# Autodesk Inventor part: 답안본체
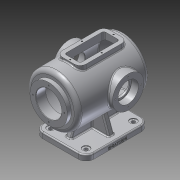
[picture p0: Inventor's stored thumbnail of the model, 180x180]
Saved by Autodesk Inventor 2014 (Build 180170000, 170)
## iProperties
Created: 2021-11
Part Number: 답안본체
Material: 알루미늄 6061
Document SubType Name: Modeling
Designer: kb
Density: 2.71 g/cm^3
Appearance: 알루미늄 - 평지
Mass: 3553.3 g
Surface Area: 2413.01 cm^2
Volume: 1311.18 cm^3
Author: kb
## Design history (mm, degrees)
sketch "스케치1"
  geometry: L1 (0, 0)-(220, 0); L2 (185.993, 65)-(10, 65); L3 (10, 65)-(10, 47.5); L4 (10, 47.5)-(0, 47.5); L5 (0, 47.5)-(0, 32.5); L6 (0, 32.5)-(25, 32.5); L7 (25, 32.5)-(25, 52); L8 (28, 55)-(179.75, 55); A1 r 100 centre (110, 0) between (210, 0) and (185.993, 65); A2 r 90 centre (110, 0) between (200, 0) and (182.155, 53.793); A3 r 3 centre (28, 52) between (28, 55) and (25, 52); A4 r 3 centre (179.75, 52) between (182.155, 53.793) and (179.75, 55); 2 further points
  constraints: 16 end point, 9 point on circle, 5 point on line, 4 centre point, 4 perpendicular, 4 tangent, 2 parallel, 1 coincident, 1 horizontal, 1 midpoint, 1 vertical alignment
  dimensions: "d0" = 130 diameter of L2 L1; "d2" = 95 diameter of L4 L1; "d3" = 110 diameter of L8 L1; "d4" = 65 diameter of L6 L1; "d6" = 10 distance of L3.end L4.end; "d9" = 25 distance between parallel lines of L7 L5; "d13" = 100 radius of A1; "d14" = 10 radial gap between concentric circles of A1 A2; "d15" = 210 distance from line of A1.start L5; "d17" = 3 radius of A3; "d18" = 3 radius of A4
revolve "회전1" sketch "스케치1" stored, may be unused: angle "d10" = 90 deg
fillet "모깎기1" dims "d16" = 10
node "작업 평면1"
sketch "스케치2"
  geometry: L1 (47.5, 0)-(-47.5, 0) reference; L2 (-45, 190)-(45, 190); L3 (65, 170)-(65, 50); L4 (45, 30)-(-45, 30); L5 (-65, 50)-(-65, 170); A1 r 100 centre (0, 110) between (61.111, 189.154) and (-61.111, 189.154) reference; A2 r 20 centre (-45, 170) between (-45, 190) and (-65, 170); A3 r 20 centre (-45, 50) between (-65, 50) and (-45, 30); A4 r 20 centre (45, 50) between (45, 30) and (65, 50); A5 r 20 centre (45, 170) between (65, 170) and (45, 190); 9 further points
  constraints: 8 end point, 8 point on circle, 8 tangent, 6 point on line, 4 centre point, 4 coincident, 3 equal radius, 2 parallel, 1 horizontal, 1 midpoint, 1 perpendicular, 1 vertical alignment
  dimensions: "d20" = 130 distance of point (-65, 190) point (65, 190); "d21" = 160 distance of point (65, 190) point (65, 30); "d22" = 30 distance between parallel lines of L4 L1; "d23" = 20 radius of A2
extrude "돌출1" join sketch "스케치2" distance "d24" = 14; taper "d25" = 0 deg
sketch "스케치3"
  geometry: A1 r 20 centre (-45, 50) between (-65, 50) and (-45, 30) reference; A2 r 20 centre (45, 50) between (45, 30) and (65, 50) reference; A3 r 20 centre (45, 170) between (65, 170) and (45, 190) reference; A4 r 20 centre (-45, 170) between (-45, 190) and (-65, 170) reference; 5 further points
  constraints: 4 coincident
hole "구멍1" sketch "스케치3" at (-45, 50), (45, 170), (45, 50), (-45, 170) diameter "d26" = 9; stored, may be unused: countersink angle "d30" = 90 deg, drill point angle "d32" = 118 deg; dims "d27" = 6, "d28" = 18, "d29" = 2, "d31" = 12
node "작업 평면2"
sketch "스케치4"
  geometry: L1 (45, 114)-(45, -1.6); L2 (90, 14)-(0, 14) reference; L3 (11.261, 58.442)-(-5, 13.765); L4 (78.739, 58.442)-(95, 13.765); L5 (110, 14)-(90, 14) reference; L6 (-9, 14)-(9, 14) reference; L7 (-5, 13.765)-(95, 13.765); L8 (94.5, 12)-(85.5, 12) reference; A1 r 65 centre (45, 114) between (11.261, 58.442) and (11.261, 58.442) reference; A2 r 65 centre (45, 114) between (11.261, 58.442) and (78.739, 58.442); 2 further points
  constraints: 8 end point, 4 point on circle, 2 symmetric about line, 1 centre point, 1 concentric, 1 midpoint, 1 parallel, 1 perpendicular, 1 vertical alignment, 1 other
  dimensions: "d40" = 100 distance of L4.end L3.end; "d41" = 110 deg angle of L5 L4; "d42" = 110 deg angle of L6 L3 (derived); "d43" = 14.17568 distance from line of L5.start L4; "d44" = 15.60038 distance from line of L1.end L2
sketch "스케치5"
  geometry: 1 further point
extrude "돌출3" join sketch "스케치4" stored distance "d45" = 14; taper "d46" = 0 deg
sketch "스케치6"
  geometry: L1 (20, -65)-(181.239, -65) reference; L2 (170, -100)-(50, -100) reference; L3 (62.739, -65)-(50, -100); L4 (41, -100)-(59, -100) reference; L5 (190, -100)-(170, -100) reference; L6 (157.261, -65)-(170, -100); L7 (103, -100)-(117, -100) reference; L8 (103, -55.558)-(103, -100) reference; L9 (117, -55.558)-(103, -55.558) reference; L10 (117, -100)-(117, -55.558) reference; L11 (117, -100)-(117, -55.558) reference; L12 (110, -55.558)-(110, -100); 1 further point
  constraints: 6 end point, 3 midpoint, 2 point on line, 1 other
  dimensions: "d117" = 120 distance of L2.start L2.end (derived); "d118" = 110 deg angle of L5 L6
  node "투영된 루프1"
feature "리브1" dims "d50" = 1, "d51" = 14, "d52" = 0, "d53" = 0, "d54" = 1, "d55" = 1
feature "리브2" dims "d56" = 1, "d57" = 14, "d58" = 0, "d59" = 0, "d60" = 1, "d61" = 1
node "작업 평면3"
sketch "스케치7"
  geometry: L1 (0, -47.5)-(0, 47.5) reference; C1 r 40 at (127, 0); 2 further points
  constraints: 1 centre point, 1 horizontal alignment, 1 midpoint
  dimensions: "d63" = 127 distance from line of C1.centre L1; "d64" = 80 diameter of C1
extrude "돌출4" join sketch "스케치7" stored distance "d65" = 14; taper "d66" = 0 deg
hole "구멍2" diameter "d69" = 42; stored, may be unused: countersink angle "d73" = 90 deg, drill point angle "d75" = 118 deg; dims "d67" = 10, "d68" = 10, "d70" = 6, "d71" = 52, "d72" = 18, "d74" = 12
fillet "모깎기2" dims "d76" = 0.3
node "작업 평면4"
sketch "스케치8"
  geometry: L1 (-15, 170)-(15, 170); L2 (30, 155)-(30, 65); L3 (15, 50)-(-15, 50); L4 (-30, 65)-(-30, 155); L5 (47.5, 0)-(-47.5, 0) reference; A1 r 15 centre (-15, 155) between (-15, 170) and (-30, 155); A2 r 15 centre (-15, 65) between (-30, 65) and (-15, 50); A3 r 15 centre (15, 65) between (15, 50) and (30, 65); A4 r 15 centre (15, 155) between (30, 155) and (15, 170); 5 further points
  constraints: 8 end point, 8 point on circle, 8 tangent, 6 point on line, 4 centre point, 3 equal radius, 2 parallel, 1 horizontal, 1 midpoint, 1 perpendicular, 1 vertical alignment
  dimensions: "d78" = 120 distance of point (30, 170) point (30, 50); "d79" = 60 distance of point (-30, 170) point (30, 170); "d80" = 50 distance between parallel lines of L3 L5; "d81" = 15 radius of A1
extrude "돌출5" join sketch "스케치8" stored distance "d82" = 14; taper "d83" = 0 deg
sketch "스케치9"
  geometry: L1 (-30, 155)-(-30, 65) reference; L2 (-15, 50)-(15, 50) reference; L3 (30, 65)-(30, 155) reference; L4 (15, 170)-(-15, 170) reference; L5 (20, 155)-(20, 65); L6 (15, 60)-(-15, 60); L7 (-20, 65)-(-20, 155); L8 (-15, 160)-(15, 160); A1 r 15 centre (-15, 65) between (-30, 65) and (-15, 50) reference; A2 r 15 centre (15, 65) between (15, 50) and (30, 65) reference; A3 r 15 centre (15, 155) between (30, 155) and (15, 170) reference; A4 r 15 centre (-15, 155) between (-15, 170) and (-30, 155) reference; A5 r 5 centre (15, 155) between (20, 155) and (15, 160); A6 r 5 centre (15, 65) between (15, 60) and (20, 65); A7 r 5 centre (-15, 65) between (-20, 65) and (-15, 60); A8 r 5 centre (-15, 155) between (-15, 160) and (-20, 155); 1 further point
  constraints: 8 end point, 8 point on circle, 4 centre point, 7 other
  dimensions: "d84" = 10 distance between parallel lines of L3 L5
extrude "돌출6" cut sketch "스케치9" stored distance "d85" = 14; taper "d86" = 0 deg
sketch "스케치10"
  geometry: L1 (-30, 155)-(-30, 65) reference; L2 (-15, 50)-(15, 50) reference; L3 (30, 65)-(30, 155) reference; L4 (15, 170)-(-15, 170) reference; L5 (25, 155)-(25, 65); L6 (15, 55)-(-15, 55); L7 (-25, 65)-(-25, 155); L8 (-15, 165)-(15, 165); L9 (-25, 110)-(25, 110); L10 (0, 165)-(0, 55); A1 r 15 centre (-15, 65) between (-30, 65) and (-15, 50) reference; A2 r 15 centre (15, 65) between (15, 50) and (30, 65) reference; A3 r 15 centre (15, 155) between (30, 155) and (15, 170) reference; A4 r 15 centre (-15, 155) between (-15, 170) and (-30, 155) reference; A5 r 10 centre (15, 65) between (15, 55) and (25, 65); A6 r 10 centre (-15, 65) between (-25, 65) and (-15, 55); A7 r 10 centre (-15, 155) between (-15, 165) and (-25, 155); A8 r 10 centre (15, 155) between (25, 155) and (15, 165); 9 further points; 1 other entity
  constraints: 12 end point, 8 point on circle, 5 coincident, 4 centre point, 4 midpoint, 8 other
  dimensions: "d87" = 5 distance between parallel lines of L3 L5
hole "구멍3" sketch "스케치10" at (-25, 110), (0, 55), (25, 110), (0, 165) diameter "d88" = 3.242; stored, may be unused: countersink angle "d92" = 90 deg, drill point angle "d94" = 118 deg; dims "d89" = 9, "d90" = 52, "d91" = 18, "d93" = 11
sketch "스케치11"
  geometry: C1 r 26 at (0, 0) reference; C2 r 40 at (0, 0) reference; A1 r 32.5 centre (0, 0) between (0, 32.5) and (-32.5, 0); 3 further points
  constraints: 4 point on circle, 2 horizontal alignment, 2 vertical alignment, 1 centre point, 1 coincident
  dimensions: "d95" = 65 diameter of A1
hole "구멍4" sketch "스케치11" at (-32.5, 0), (0, -32.5), (32.5, 0), (0, 32.5) diameter "d96" = 3.242; stored, may be unused: countersink angle "d100" = 90 deg, drill point angle "d102" = 118 deg; dims "d97" = 11, "d98" = 52, "d99" = 18, "d101" = 13
sketch "스케치12"
  geometry: C1 r 32.5 at (0, 0) reference; C2 r 47.5 at (0, 0) reference; A1 r 40 centre (0, 0) between (0, 40) and (0, -40); 2 further points
  constraints: 4 point on circle, 2 horizontal alignment, 2 vertical alignment, 1 centre point, 1 coincident
  dimensions: "d103" = 80 diameter of A1
hole "구멍5" sketch "스케치12" at (0, 40), (-40, 0), (0, -40), (40, 0) diameter "d104" = 3.242; stored, may be unused: countersink angle "d108" = 90 deg, drill point angle "d110" = 118 deg; dims "d105" = 11, "d106" = 52, "d107" = 18, "d109" = 13
fillet "모깎기3" dims "d111" = 3
fillet "모깎기4" dims "d112" = 3
node "작업 평면5"
sketch "스케치13" dims "d20" = 130, "d21" = 160, "d22" = 30, "d23" = 20
  geometry: L1 (0, 0)-(0, 120) reference; 3 further points
  constraints: 1 horizontal alignment, 1 midpoint, 1 other
  dimensions: "d114" = 5 distance from line of L1 point (-5, 60)
feature "엠보싱1" sketch "스케치13" dims "d115" = 0.5, "d116" = 0
chamfer "모따기1" distance "d119" = 1; stored, may be unused: second distance "d120" = 2, angle "d121" = 45 deg
node "솔리드1"
mirror "대칭1"
mirror "대칭2"
other parameters: "d19" = -114, "d62" = 75, "d113" = 48.25
